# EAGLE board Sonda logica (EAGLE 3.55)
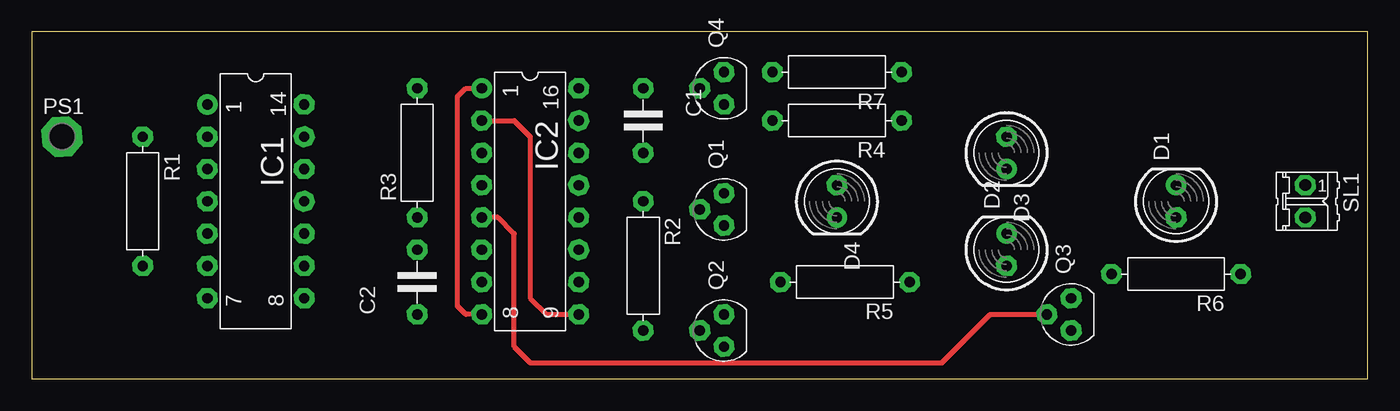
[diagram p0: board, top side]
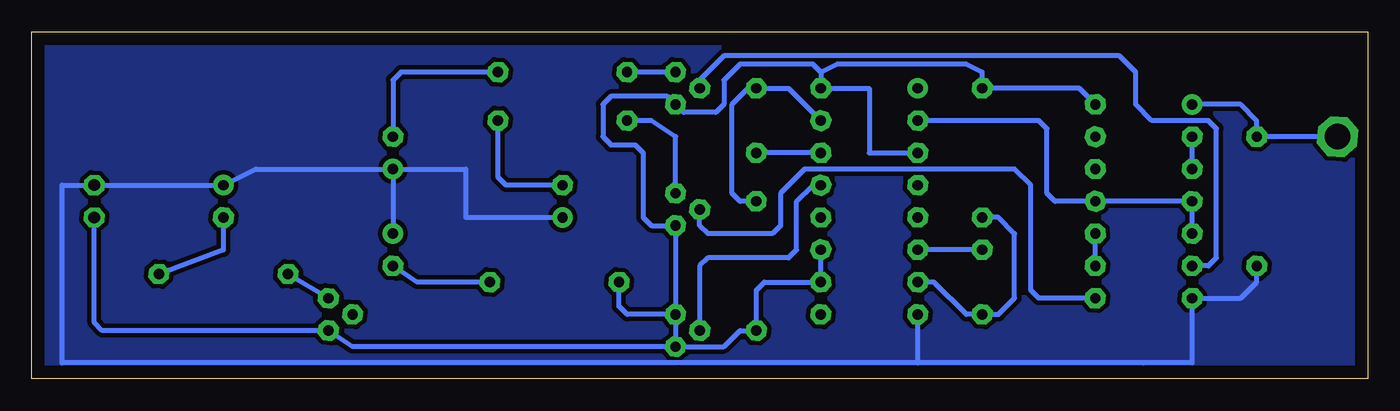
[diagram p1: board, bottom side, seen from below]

Size 105.08 x 27.3 mm. Coordinates in mm from the lower left corner, seen from the top.
Outline: 0,0 105.08,0 105.08,27.3 0,27.3 0,0
Copper layers used: Top, Bottom

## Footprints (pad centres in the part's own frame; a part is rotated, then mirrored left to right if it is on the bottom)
5 = drill 0.813 pad 1.6 octagon:  -2.54,0;  2.54,0
D5 = drill 0.813 pad 1.6 octagon:  -1.27,0 | drill 0.813 pad 1.6 round:  1.27,0
L14 = drill 0.813 pad 1.6 round:  -7.62,-3.81 | drill 0.813 pad 1.6 octagon:  -5.08,-3.81;  -2.54,-3.81;  0,-3.81;  2.54,-3.81;  5.08,-3.81;  7.62,-3.81;  7.62,3.81;  5.08,3.81;  2.54,3.81;  0,3.81;  -2.54,3.81;  -5.08,3.81;  -7.62,3.81
L16 = drill 0.813 pad 1.6 round:  -8.89,-3.81 | drill 0.813 pad 1.6 octagon:  -6.35,-3.81;  -3.81,-3.81;  -1.27,-3.81;  1.27,-3.81;  3.81,-3.81;  6.35,-3.81;  8.89,-3.81;  8.89,3.81;  6.35,3.81;  3.81,3.81;  1.27,3.81;  -1.27,3.81;  -3.81,3.81;  -6.35,3.81;  -8.89,3.81
-20 = drill 2.007 pad 3.15 octagon:  0,0
T54A = drill 0.813 pad 1.6 octagon:  -1.27,0;  0,1.905;  1.27,0
10 = drill 0.813 pad 1.6 octagon:  -5.08,0;  5.08,0
P = drill 0.914 pad 1.6 octagon:  -1.27,0;  1.27,0

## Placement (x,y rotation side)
C1  1uF  [5]  48.09,20.32 270 top
C2  1uF  [5]  30.32,7.61 90 top
D1  LED5  [D5]  90.01,13.96 90 top
D2  LED5  [D5]  76.67,10.16 90 top
D3  LED5  [D5]  76.67,17.78 270 top
D4  LED5  [D5]  63.33,13.96 270 top
IC1  74C04  [L14]  17.62,13.96 270 top
IC2  74C123  [L16]  39.2,13.96 270 top
PS1  P1-20  [-20]  2.38,19.05 0 top
Q1  BC547  [T54A]  54.45,13.33 90 top
Q2  BC547  [T54A]  54.45,3.8 90 top
Q3  BC547  [T54A]  81.75,5.08 90 top
Q4  BC547  [T54A]  54.45,22.86 90 top
R1  100K  [10]  8.72,13.96 270 top
R2  100K  [10]  48.09,8.88 270 top
R3  100K  [10]  30.32,17.78 90 top
R4  470  [10]  63.33,20.32 180 top
R5  470  [10]  63.97,7.61 180 top
R6  470  [10]  90.01,8.25 180 top
R7  470  [10]  63.33,24.12 180 top
SL1  M02  [P]  100.17,13.96 270 top

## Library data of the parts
C1 C2 R1-R7 = discrete
D1-D4 = led
IC1 IC2 = 74xx
PS1 = testpad
Q1-Q4 = trans-sm
SL1 = conquick

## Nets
GND: D1. D2. D3. D4. IC1. IC2. R1. SL1.
N$1: IC1. Q4.
N$2: Q1. R4.
N$3: IC1.
N$4: D4. R4.
N$5: IC1. PS1. R1.
N$6: IC1.
N$7: IC2. Q2.
N$8: C1. IC2.
N$9: C1. IC2. R2.
N$10: IC2. Q3.
N$11: C2. IC2. R3.
N$12: C2. IC2.
N$13: Q3. R6.
N$14: IC1. IC2.
N$15: Q2. R5.
N$16: D2. R5.
N$17: D1. R6.
N$19: IC1. Q1.
N$20: Q4. R7.
N$21: D3. R7.
VCC: IC1. IC2. Q1. Q2. Q3. Q4. R2. R3. SL1.

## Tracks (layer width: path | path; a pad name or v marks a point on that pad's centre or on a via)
GND
  Top 0.406: 35.39,5.08 34.12,5.08 33.49,5.71 33.49,22.22 34.12,22.86 35.39,22.86
  Bottom 0.406: R1. 8.72,7.61 10,6.34 13.8,6.34 13.8,1.26 17.62,1.26 35.39,1.26 | D3. 87.47,16.5 D1. 100.17,15.24 102.7,15.24 102.7,1.26 35.39,1.26 | D3. 70.95,16.5 70.95,12.7 D4. | 35.39,1.26 35.39,5.08 | D3. D2.
  pour Bottom (isolate 0.356): 0.47,26.66 0.47,0.63 104.61,0.63 104.61,26.66
N$1
  Bottom 0.406: 52.54,22.86 52.54,23.49 50.63,25.39 19.52,25.39 18.25,24.12 18.25,21.59 16.98,20.32 12.54,20.32 11.9,19.68 11.9,9.52 12.54,8.88 13.8,8.88
N$2
  Bottom 0.406: Q1. 54.45,19.05 56.35,20.32 R4.
N$3
  Bottom 0.406: 21.43,8.88 21.43,11.43
N$4
  Bottom 0.406: 63.33,15.24 67.78,15.24 68.42,15.87 68.42,20.32
N$5
  Bottom 0.406: 13.8,21.59 10,21.59 8.72,20.32 8.72,19.05 PS1.
N$6
  Bottom 0.406: 13.8,16.5 13.8,19.05
N$7
  Bottom 0.406: 52.54,3.8 52.54,8.88 51.9,9.52 45.55,9.52 44.92,10.16 44.92,13.96 43.65,15.24 43.01,15.24
N$8
  Bottom 0.406: 43.01,17.78 C1.
N$9
  Bottom 0.406: 43.01,20.32 45.55,22.86 48.09,22.86 48.73,22.86 50,21.59 50,14.6 49.36,13.96 48.09,13.96
N$10
  Top 0.406: 35.39,12.7 36.66,12.7 37.93,11.43 37.93,2.54 39.2,1.26 71.59,1.26 75.4,5.08 79.84,5.08
N$11
  Bottom 0.406: 35.39,7.61 34.12,7.61 31.59,5.08 30.32,5.08 29.05,5.08 27.78,6.34 27.78,11.43 29.05,12.7 30.32,12.7
N$12
  Bottom 0.406: C2. 35.39,10.16
N$13
  Bottom 0.406: Q3. R6.
N$14
  Top 0.406: 35.39,20.32 37.93,20.32 39.2,19.05 39.2,6.34 40.47,5.08 43.01,5.08
  Bottom 0.406: 35.39,20.32 25.87,20.32 25.23,19.68 25.23,14.6 24.6,13.96 21.43,13.96 13.8,13.96 13.8,11.43
N$15
  Bottom 0.406: R5. 58.89,5.71 58.25,5.08 Q2.
N$16
  Bottom 0.406: 76.67,8.88 74.77,7.61 69.05,7.61
N$17
  Bottom 0.406: 95.09,8.25 90.01,10.16 90.01,12.7
N$19
  Bottom 0.406: 21.43,6.34 25.87,6.34 26.5,6.98 26.5,15.24 27.78,16.5 44.28,16.5 46.19,14.6 46.19,12.06 46.82,11.43 51.9,11.43 52.54,12.06 52.54,13.33
N$20
  Bottom 0.406: Q4. R7.
N$21
  Bottom 0.406: 68.42,24.12 76.04,24.12 76.67,23.49 76.67,19.05
VCC
  Bottom 0.406: IC1. 22.7,22.86 R3. 30.32,24.12 31.59,24.76 41.74,24.76 43.01,24.12 | 54.45,2.54 50.63,2.54 49.36,3.8 R2. 48.09,6.98 47.46,7.61 43.01,7.61 43.01,10.16 | 54.45,2.54 54.45,12.06 56.35,12.06 56.98,12.7 56.98,17.78 57.62,18.41 59.52,18.41 60.16,19.05 60.16,21.59 59.52,22.22 55.08,22.22 54.45,21.59 53.81,20.95 51.27,20.95 50.63,21.59 50.63,23.49 49.36,24.76 43.65,24.76 43.01,24.12 | 54.45,2.54 79.84,2.54 81.75,3.8 99.53,3.8 100.17,4.44 SL1. | 43.01,24.12 IC2. 39.2,22.86 39.2,17.78 35.39,17.78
